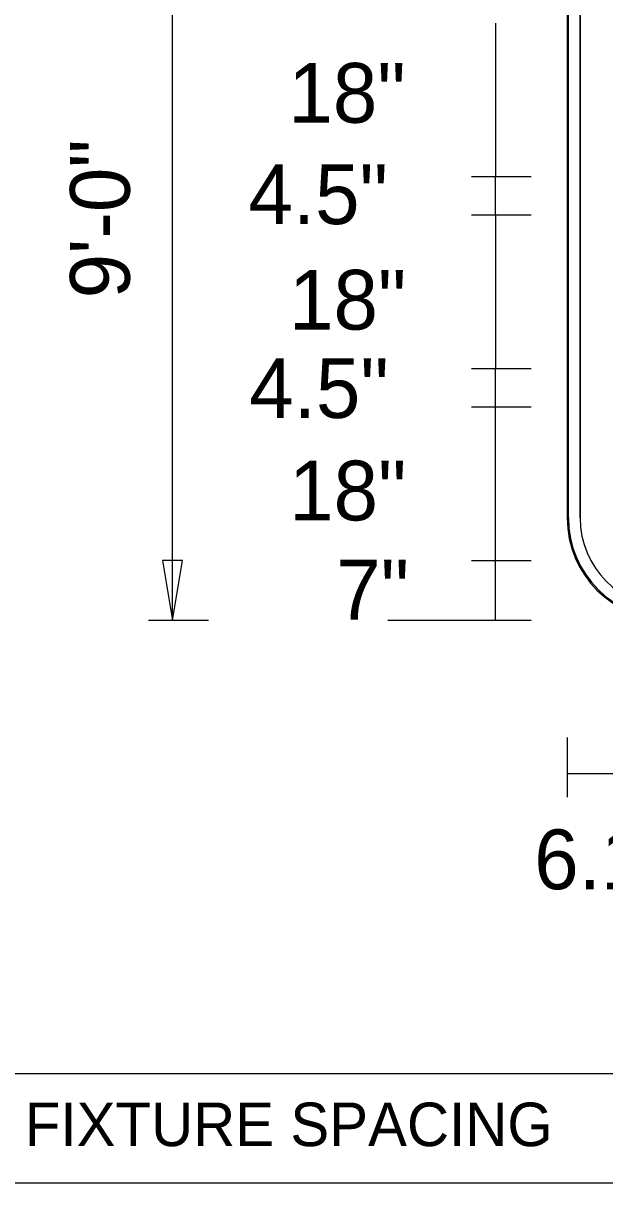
# Model space of a CAD drawing. Extents: x 17890628 to 17891459, y 17897314 to 17897992.
# Drawn here: x 17890794.41 to 17890800.08, y 17897475.66 to 17897486.98 of the extents above; entities that cross this region are included whole.
import ezdxf

# ---------------------------------------------------------------- set-up
doc = ezdxf.new("R2010")
doc.units = 0
for name, color, linetype in [('GSColorFill', 7, 'Continuous'), ('GSDims', 7, 'Continuous'), ('GSOutline', 7, 'Continuous'), ('SheetLinesMisc2_dp', 7, 'Continuous'), ('TextMinor', 7, 'Continuous'), ('XSCell', 7, 'Continuous')]:
    doc.layers.add(name, color=color, linetype=linetype)

msp = doc.modelspace()

# ---------------------------------------------------------------- linework, layer by layer
at = {"layer": 'GSColorFill'}
for p, q in [((17890799.716, 17897489.153), (17890799.716, 17897482.153)), ((17890799.716, 17897489.153), (17890799.716, 17897482.153)), ((17890799.716, 17897489.153), (17890799.716, 17897482.153)), ((17890799.728, 17897482.153), (17890799.728, 17897489.153)), ((17890799.841, 17897482.153), (17890799.841, 17897489.153))]:
    msp.add_line(p, q, dxfattribs=at)
for radius in [1, 1, 1, 0.988, 0.875]:
    msp.add_arc((17890800.716, 17897482.153), radius, 180, 270, dxfattribs=at)
at = {"layer": 'GSDims'}
for p, q in [((17890795.866, 17897481.153), (17890795.866, 17897490.153)), ((17890799.016, 17897486.984), (17890799.016, 17897485.484)), ((17890799.366, 17897485.484), (17890798.782, 17897485.484)), ((17890799.016, 17897485.109), (17890799.016, 17897485.484)), ((17890799.016, 17897485.109), (17890799.016, 17897485.484)), ((17890799.016, 17897485.109), (17890799.016, 17897485.484)), ((17890799.016, 17897485.109), (17890799.016, 17897485.484)), ((17890799.366, 17897485.109), (17890798.782, 17897485.109)), ((17890799.016, 17897485.109), (17890799.016, 17897483.609)), ((17890799.366, 17897483.609), (17890798.782, 17897483.609)), ((17890799.366, 17897483.609), (17890798.782, 17897483.609)), ((17890799.366, 17897483.609), (17890798.782, 17897483.609)), ((17890799.366, 17897483.609), (17890798.782, 17897483.609)), ((17890799.366, 17897483.609), (17890798.782, 17897483.609)), ((17890799.366, 17897483.609), (17890798.782, 17897483.609)), ((17890799.366, 17897483.609), (17890798.782, 17897483.609)), ((17890799.366, 17897483.609), (17890798.782, 17897483.609)), ((17890799.366, 17897483.609), (17890798.782, 17897483.609)), ((17890799.366, 17897483.609), (17890798.782, 17897483.609)), ((17890799.016, 17897481.153), (17890799.016, 17897483.609)), ((17890799.366, 17897483.234), (17890798.782, 17897483.234)), ((17890799.366, 17897481.734), (17890798.782, 17897481.734)), ((17890796.216, 17897481.153), (17890795.632, 17897481.153)), ((17890796.216, 17897481.153), (17890795.632, 17897481.153)), ((17890796.216, 17897481.153), (17890795.632, 17897481.153)), ((17890796.216, 17897481.153), (17890795.632, 17897481.153)), ((17890796.216, 17897481.153), (17890795.632, 17897481.153)), ((17890799.366, 17897481.153), (17890797.966, 17897481.153)), ((17890799.366, 17897481.153), (17890797.966, 17897481.153)), ((17890799.366, 17897481.153), (17890797.966, 17897481.153)), ((17890799.366, 17897481.153), (17890797.966, 17897481.153)), ((17890799.366, 17897481.153), (17890797.966, 17897481.153)), ((17890799.366, 17897481.153), (17890798.782, 17897481.153)), ((17890799.366, 17897481.153), (17890798.782, 17897481.153)), ((17890799.366, 17897481.153), (17890798.782, 17897481.153)), ((17890799.366, 17897481.153), (17890798.782, 17897481.153)), ((17890799.366, 17897481.153), (17890798.782, 17897481.153)), ((17890799.716, 17897480.009), (17890799.716, 17897479.426)), ((17890799.716, 17897480.009), (17890799.716, 17897479.426)), ((17890799.716, 17897479.659), (17890800.223, 17897479.659))]:
    msp.add_line(p, q, dxfattribs=at)
msp.add_lwpolyline([(17890795.866, 17897481.153), (17890795.963, 17897481.736), (17890795.768, 17897481.736)], close=True, dxfattribs=at)
at = {"layer": 'GSOutline'}
for p, q in [((17890799.716, 17897489.153), (17890799.716, 17897482.153)), ((17890799.841, 17897482.153), (17890799.841, 17897489.153))]:
    msp.add_line(p, q, dxfattribs=at)
for radius in [1, 0.875]:
    msp.add_arc((17890800.716, 17897482.153), radius, 180, 270, dxfattribs=at)
at = {"layer": 'SheetLinesMisc2_dp'}
for p, q in [((17890784.715, 17897476.729), (17890825.647, 17897476.729)), ((17890784.715, 17897475.661), (17890825.647, 17897475.661))]:
    msp.add_line(p, q, dxfattribs=at)
at = {"layer": 'XSCell'}
for p, q in [((17890799.716, 17897489.153), (17890799.716, 17897482.153)), ((17890799.841, 17897489.153), (17890799.841, 17897482.153))]:
    msp.add_line(p, q, dxfattribs=at)
for radius in [1, 0.875]:
    msp.add_arc((17890800.716, 17897482.153), radius, 180, 270, dxfattribs=at)

# ---------------------------------------------------------------- texts
at = {"layer": 'GSDims'}
for s, p in [('18"', (17890796.996, 17897486.012)), ('4.5"', (17890796.606, 17897485.022)), ('18"', (17890797.002, 17897483.992)), ('4.5"', (17890796.614, 17897483.129)), ('18"', (17890797.003, 17897482.129)), ('7"', (17890797.463, 17897481.161)), ('6.1"', (17890799.394, 17897478.528))]:
    msp.add_text(s, height=0.5833, dxfattribs=at).set_placement(p)
msp.add_text('9\'-0"', height=0.5833, rotation=90, dxfattribs=at).set_placement((17890795.449, 17897484.297))
at = {"layer": 'TextMinor'}
msp.add_text('FIXTURE SPACING', height=0.42516, dxfattribs=at).set_placement((17890794.425, 17897476.019))

doc.saveas('drawing.dxf')
